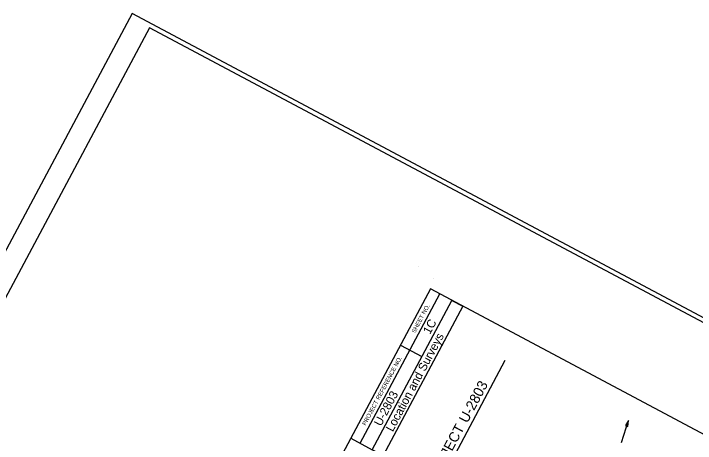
# Model space of a CAD drawing. Extents: x 1970823 to 1988115, y 770601 to 786368.
# Drawn here: x 1974849 to 1979025, y 783732 to 786368 of the extents above; entities that cross this region are included whole.
import ezdxf

# ---------------------------------------------------------------- set-up
doc = ezdxf.new("R2010")
doc.units = 0
for name, color, linetype in [('CTL Sheet Border CELL', 7, 'Continuous'), ('CTL Sheet Text', 7, 'Continuous'), ('Old_Level_50', 7, 'Continuous'), ('Old_Level_51', 7, 'Continuous'), ('Sheet Data Field CELL', 7, 'Continuous')]:
    doc.layers.add(name, color=color, linetype=linetype)

msp = doc.modelspace()

# ---------------------------------------------------------------- linework, layer by layer
at = {"layer": 'CTL Sheet Border CELL'}
msp.add_lwpolyline([(1977401.8, 784679.3), (1973721.3, 777772.6), (1978555.9, 775196.3), (1982236.4, 782102.9)], close=True, dxfattribs=at)
at = {"layer": 'CTL Sheet Text'}
for p, q in [((1977858.8, 784239.4), (1977193.9, 782991.6)), ((1978571.9, 783736.8), (1978614.9, 783873.4))]:
    msp.add_line(p, q, dxfattribs=at)
msp.add_lwpolyline([(1978596.4, 783841.3), (1978611.7, 783836.4), (1978614.9, 783873.4)], close=True, dxfattribs=at)
at = {"layer": 'Old_Level_50'}
msp.add_lwpolyline([(1975680.9, 786280.6), (1970978.5, 777456.3), (1976565.4, 774479.1), (1981267.8, 783303.4)], close=True, dxfattribs=at)
at = {"layer": 'Old_Level_51'}
msp.add_lwpolyline([(1975574.8, 786367.7), (1970823, 777450.8), (1976647.6, 774346.9), (1981399.3, 783263.8)], close=True, dxfattribs=at)
at = {"layer": 'Sheet Data Field CELL'}
for p, q in [((1977328.4, 784818.9), (1977328.4, 784818.9)), ((1977420.7, 784743.1), (1977420.7, 784743.1)), ((1977420.7, 784743.1), (1977420.7, 784743.1)), ((1976971.5, 783732.6), (1977459.6, 784648.5)), ((1977218, 784333.9), (1977349, 784264)), ((1976913.9, 783763.3), (1977044.9, 783693.4))]:
    msp.add_line(p, q, dxfattribs=at)
msp.add_lwpolyline([(1977044.9, 783693.4), (1977533, 784609.3), (1977600.8, 784573.2), (1977112.7, 783657.3)], close=True, dxfattribs=at)

# ---------------------------------------------------------------- texts
at = {"layer": 'CTL Sheet Text'}
for s, height, p in [('U-2803', 62.61, (1977627.8, 783852.2)), ('END STATE PROJECT ', 62.606, (1977197.4, 783048.1))]:
    msp.add_text(s, height=height, rotation=61.9471, dxfattribs=at).set_placement(p)
at = {"layer": 'Sheet Data Field CELL'}
for s, height, p in [('SHEET NO.', 26.09, (1977308.1, 784405.9)), ('1C', 52.17, (1977399.4, 784397.2)), ('Location and Surveys', 52.175, (1977171.4, 783799.6)), ('PROJECT REFERENCE NO.', 26.087, (1977005.5, 783839.1)), ('U-2803', 52.17, (1977099.1, 783833.5))]:
    msp.add_text(s, height=height, rotation=61.9471, dxfattribs=at).set_placement(p)

doc.saveas('drawing.dxf')
